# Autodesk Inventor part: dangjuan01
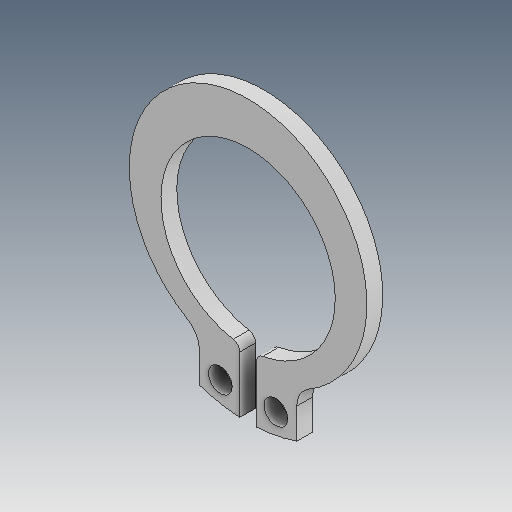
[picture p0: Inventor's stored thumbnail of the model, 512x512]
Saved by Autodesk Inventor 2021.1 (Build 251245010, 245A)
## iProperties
Created: 2018-07
Part Number: dangjuan01
Material: Ogólny
Document SubType Name: Modeling
Designer: user
Density: 1 g/cm^3
Appearance: Domyślna
Author: user
Revision Number: ÈÎºÎ
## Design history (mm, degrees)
feature "Í¹Ì¨-À­Éì1"
node "Bryła1"
